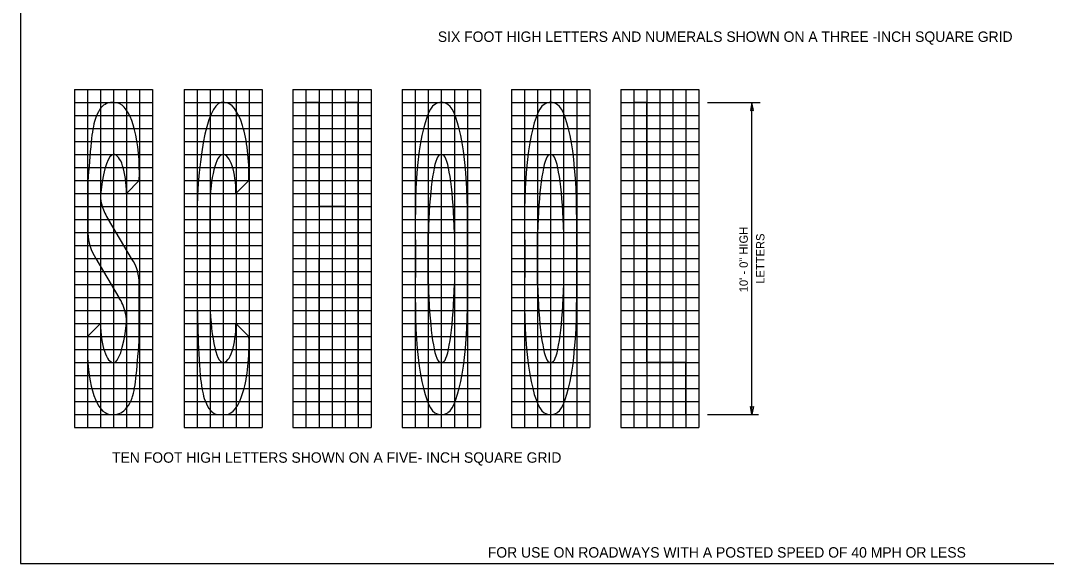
# Model space of a CAD drawing. Extents: x 99862 to 103151, y 100000 to 102076.
# Drawn here: x 99862 to 101833, y 100000 to 101043 of the extents above; entities that cross this region are included whole.
import ezdxf

# ---------------------------------------------------------------- set-up
doc = ezdxf.new("R2010")
doc.units = 0
for name, color, linetype in [('Level 1', 7, 'Continuous'), ('Level 15', 7, 'Continuous'), ('Level 20', 7, 'Continuous'), ('Level 4', 7, 'Continuous'), ('Level 60', 7, 'Continuous')]:
    doc.layers.add(name, color=color, linetype=linetype)

msp = doc.modelspace()

# ---------------------------------------------------------------- linework, layer by layer
at = {"layer": 'Level 1'}
msp.add_lwpolyline([(99862, 99999.5), (103151, 99999.5), (103151, 102075.5), (99862, 102075.5)], close=True, dxfattribs=at)
at = {"layer": 'Level 15'}
for p, q in [((101181.5, 100885.5), (101283.1, 100885.5)), ((101267.1, 100285.5), (101267.1, 100885.5)), ((101181.5, 100285.5), (101279.8, 100285.5))]:
    msp.add_line(p, q, dxfattribs=at)
for points in [[(101267.1, 100885.5), (101264.1, 100869.8), (101267.1, 100870.5), (101270.2, 100869.8)], [(101267.1, 100285.5), (101264.1, 100301.2), (101267.1, 100300.5), (101270.2, 100301.2)]]:
    msp.add_lwpolyline(points, close=True, dxfattribs=at)
at = {"layer": 'Level 20'}
for p, q in [((100254.1, 100885.5), (100247.5, 100885.5)), ((100065.6, 100710.5), (100090.2, 100735.5)), ((100275.9, 100710.5), (100300.8, 100735.5)), ((100226.1, 100510.5), (100226.1, 100685.5)), ((100075.5, 100585.5), (100031.3, 100660.2)), ((100620.4, 100658.9), (100620.5, 100585.5)), ((100720.4, 100585.5), (100720.4, 100658.9)), ((100830.4, 100658.9), (100830.5, 100585.5)), ((100830.4, 100658.9), (100830.5, 100585.5)), ((100930.4, 100585.5), (100930.4, 100658.9)), ((100930.4, 100585.5), (100930.4, 100658.9)), ((100201.2, 100635.5), (100201.2, 100535.5)), ((100645.4, 100585.5), (100645.4, 100633.9)), ((100695.4, 100633.9), (100695.4, 100585.5)), ((100855.4, 100585.5), (100855.4, 100633.9)), ((100855.4, 100585.5), (100855.4, 100633.9)), ((100905.4, 100633.9), (100905.4, 100585.5)), ((100905.4, 100633.9), (100905.4, 100585.5)), ((100006.9, 100585.5), (100050.9, 100510.9)), ((100620.5, 100585.5), (100620.4, 100512.1)), ((100645.4, 100537.1), (100645.4, 100585.5)), ((100695.4, 100585.5), (100695.4, 100537.1)), ((100720.4, 100512.1), (100720.4, 100585.5)), ((100830.5, 100585.5), (100830.4, 100512.1)), ((100830.5, 100585.5), (100830.4, 100512.1)), ((100855.4, 100537.1), (100855.4, 100585.5)), ((100855.4, 100537.1), (100855.4, 100585.5)), ((100905.4, 100585.5), (100905.4, 100537.1)), ((100905.4, 100585.5), (100905.4, 100537.1)), ((100930.4, 100512.1), (100930.4, 100585.5)), ((100930.4, 100512.1), (100930.4, 100585.5)), ((100015.8, 100460.5), (99990.9, 100435.5)), ((100300.8, 100435.5), (100275.9, 100460.5)), ((100244.3, 100285.5), (100256.6, 100285.5))]:
    msp.add_line(p, q, dxfattribs=at)
for points in [[(100485.4, 100685.5), (100435.4, 100685.5), (100435.4, 100885.5), (100410.4, 100885.5), (100410.4, 100285.5), (100435.4, 100285.5), (100435.4, 100585.5), (100485.4, 100585.5), (100485.4, 100285.5), (100510.4, 100285.5), (100510.4, 100885.5), (100485.4, 100885.5)], [(101065.4, 100385.5), (101065.4, 100885.5), (101040.4, 100885.5), (101040.4, 100285.5), (101062.3, 100285.5), (101065.4, 100285.5), (101140.4, 100285.5), (101140.4, 100385.5)]]:
    msp.add_lwpolyline(points, close=True, dxfattribs=at)
for centre, major_axis, ratio, start_param, end_param in [((100092.4, 100581.3), (63, -302.3), 0.242157, 3.211303, 3.548693), ((100039.2, 100873.6), (20.3, 0), 0.586221, 0.838796, 2.384773), ((100041.9, 100736.8), (-4.7, -147.1), 0.328163, 1.572424, 3.011418), ((100251.9, 100645.6), (2.3, -240.1), 0.211336, 3.181491, 4.752287), ((100250.9, 100736.3), (-3.3, -149.2), 0.334281, 1.57277, 3.143567), ((100670.4, 100635), (6.3, -249), 0.19927, 3.270148, 4.611013), ((100657.9, 100359.5), (-13.1, -526), 0.19927, 3.02647, 3.266464), ((100670.5, 100635.1), (-6.2, -248.8), 0.19927, 1.671693, 3.012646), ((100880.4, 100635), (6.3, -249), 0.19927, 3.270148, 4.611013), ((100880.4, 100635), (6.3, -249), 0.19927, 3.270148, 4.611013), ((100867.9, 100359.5), (-13.1, -526), 0.19927, 3.02647, 3.266464), ((100867.9, 100359.5), (-13.1, -526), 0.19927, 3.02647, 3.266464), ((100880.5, 100635.1), (-6.2, -248.8), 0.19927, 1.671693, 3.012646), ((100880.5, 100635.1), (-6.2, -248.8), 0.19927, 1.671693, 3.012646), ((100026.9, 100734.6), (9.3, -133.7), 0.214782, 3.612749, 4.104614), ((100081.3, 100593.6), (5, -434), 0.21476, 4.189874, 4.38199), ((100038.1, 100656.7), (-2.5, -128.8), 0.197234, 3.13878, 4.217516), ((100040.8, 100710.3), (0.1, -75.2), 0.328816, 1.572371, 3.143168), ((100251, 100685.5), (0, -100), 0.248912, 3.141593, 4.712389), ((100251, 100710.5), (0, -75), 0.331883, 1.570796, 3.141593), ((100663.8, 100633.5), (-3.5, -150.4), 0.122012, 3.268533, 4.71248), ((100660.5, 100351.2), (-10.2, -433.9), 0.122012, 3.042541, 3.248082), ((100677.1, 100633.5), (3.5, -150.4), 0.122012, 1.570705, 3.018849), ((100873.8, 100633.5), (-3.5, -150.4), 0.122012, 3.268533, 4.71248), ((100873.8, 100633.5), (-3.5, -150.4), 0.122012, 3.268533, 4.71248), ((100870.5, 100351.2), (-10.2, -433.9), 0.122012, 3.042541, 3.248082), ((100870.5, 100351.2), (-10.2, -433.9), 0.122012, 3.042541, 3.248082), ((100887.1, 100633.5), (3.5, -150.4), 0.122012, 1.570705, 3.018849), ((100887.1, 100633.5), (3.5, -150.4), 0.122012, 1.570705, 3.018849), ((100038.1, 100656.7), (-2.5, -128.8), 0.197234, 4.217516, 4.296738), ((100027.2, 100705.8), (0, -28.6), 0.398069, 4.656791, 5.485831), ((100038.1, 100656.7), (-2.5, -128.8), 0.197234, 4.296738, 4.302967), ((100258, 100763.3), (-237.7, -81.7), 0.573901, 6.095726, 6.102518), ((100258, 100763.3), (-237.7, -81.7), 0.573901, 6.252411, 6.448452), ((100235.7, 100684.6), (-240.1, -75.8), 0.590702, 6.109362, 6.45629), ((99846.3, 100488.7), (-240, -74), 0.588453, 2.958424, 3.311229), ((100332.5, 100654.3), (-29.1, -590.5), 0.216739, 4.925571, 5.243712), ((100663.8, 100537.5), (3.5, -150.4), 0.122012, 4.712298, 6.156245), ((100677.1, 100537.5), (-3.5, -150.4), 0.122012, 0.122744, 1.570888), ((100873.8, 100537.5), (3.5, -150.4), 0.122012, 4.712298, 6.156245), ((100873.8, 100537.5), (3.5, -150.4), 0.122012, 4.712298, 6.156245), ((100887.1, 100537.5), (-3.5, -150.4), 0.122012, 0.122744, 1.570888), ((100887.1, 100537.5), (-3.5, -150.4), 0.122012, 0.122744, 1.570888), ((99812.7, 100409.9), (-248.8, -79.1), 0.572533, 3.093706, 3.30331), ((100251, 100510.5), (0, -125), 0.19913, 4.712389, 6.283185), ((100670.4, 100536), (-6.3, -249), 0.19927, 4.813765, 6.15463), ((100670.5, 100535.9), (6.2, -248.8), 0.19927, 0.128946, 1.4699), ((100880.4, 100536), (-6.3, -249), 0.19927, 4.813765, 6.15463), ((100880.4, 100536), (-6.3, -249), 0.19927, 4.813765, 6.15463), ((100880.5, 100535.9), (6.2, -248.8), 0.19927, 0.128946, 1.4699), ((100880.5, 100535.9), (6.2, -248.8), 0.19927, 0.128946, 1.4699), ((100054.1, 100465.2), (0, -28.6), 0.398069, 1.570796, 2.201234), ((100040.6, 100461.1), (-0.1, -75.6), 0.328439, 4.720548, 6.291345), ((100054.1, 100465.2), (0, -28.6), 0.398069, 1.272104, 1.406781), ((100054.1, 100465.2), (0, -28.6), 0.398069, 1.406781, 1.536547), ((100054.1, 100465.2), (0, -28.6), 0.398069, 1.536547, 1.570796), ((100251, 100460.5), (0, -75), 0.331883, 6.283185, 7.853982), ((100044.4, 100509.4), (-3.7, -123.9), 0.197285, 6.281921, 7.420926), ((100039.1, 100433.9), (-7.1, -146.7), 0.327941, 4.716992, 6.122079), ((100002, 100571.1), (7.5, -422), 0.214743, 1.047686, 1.241737), ((100251.6, 100434.2), (5.1, -148.6), 0.331181, 6.280966, 7.851763), ((100660.5, 100819.8), (10.2, -433.9), 0.122012, 6.176696, 6.382237), ((100870.5, 100819.8), (10.2, -433.9), 0.122012, 6.176696, 6.382237), ((100870.5, 100819.8), (10.2, -433.9), 0.122012, 6.176696, 6.382237), ((100055.4, 100436.4), (9.3, -133.7), 0.214782, 0.471156, 0.963021), ((100236.7, 100435.7), (-9.4, -134.4), 0.216756, 5.320454, 5.812319), ((100009.1, 100606.7), (39.3, -319.7), 0.244883, 0.082568, 0.415625), ((100303.1, 100589.7), (-63.9, -303.8), 0.244216, 5.877043, 6.350091), ((100039.9, 100297.4), (21, 0), 0.567157, 3.879554, 5.494464), ((100657.9, 100811.5), (13.1, -526), 0.19927, 6.158314, 6.398307), ((100867.9, 100811.5), (13.1, -526), 0.19927, 6.158314, 6.398307), ((100867.9, 100811.5), (13.1, -526), 0.19927, 6.158314, 6.398307)]:
    msp.add_ellipse(centre, major_axis=major_axis, ratio=ratio, start_param=start_param, end_param=end_param, dxfattribs=at)
for points in [[(99991.5, 100733.4), (99990.9, 100641.8), (99991.5, 100634.5)], [(100090.2, 100436.3), (100090.2, 100534.2), (100090.2, 100535.8)]]:
    msp.add_open_spline(points, degree=2, dxfattribs=at)
at = {"layer": 'Level 4'}
for p, q in [((99965.4, 100910.5), (99965.4, 100260.5)), ((99965.4, 100910.5), (100115.4, 100910.5)), ((99990.4, 100910.5), (99990.4, 100260.5)), ((100015.4, 100910.5), (100015.4, 100260.5)), ((100040.4, 100910.5), (100040.4, 100260.5)), ((100065.4, 100910.5), (100065.4, 100260.5)), ((100090.4, 100910.5), (100090.4, 100260.5)), ((100115.4, 100910.5), (100115.4, 100260.5)), ((100176.1, 100910.5), (100176.1, 100260.5)), ((100176.1, 100910.5), (100326.1, 100910.5)), ((100201.1, 100910.5), (100201.1, 100260.5)), ((100226.1, 100910.5), (100226.1, 100260.5)), ((100251.1, 100910.5), (100251.1, 100260.5)), ((100276.1, 100910.5), (100276.1, 100260.5)), ((100301.1, 100910.5), (100301.1, 100260.5)), ((100326.1, 100910.5), (100326.1, 100260.5)), ((100385.4, 100910.5), (100385.4, 100260.5)), ((100385.4, 100910.5), (100535.4, 100910.5)), ((100410.4, 100910.5), (100410.4, 100260.5)), ((100435.4, 100910.5), (100435.4, 100260.5)), ((100460.4, 100910.5), (100460.4, 100260.5)), ((100485.4, 100910.5), (100485.4, 100260.5)), ((100510.4, 100910.5), (100510.4, 100260.5)), ((100535.4, 100910.5), (100535.4, 100260.5)), ((100595.4, 100910.5), (100595.4, 100260.5)), ((100595.4, 100910.5), (100745.4, 100910.5)), ((100620.4, 100910.5), (100620.4, 100260.5)), ((100645.4, 100910.5), (100645.4, 100260.5)), ((100670.4, 100910.5), (100670.4, 100260.5)), ((100695.4, 100910.5), (100695.4, 100260.5)), ((100720.4, 100910.5), (100720.4, 100260.5)), ((100745.4, 100910.5), (100745.4, 100260.5)), ((100805.4, 100910.5), (100805.4, 100260.5)), ((100805.4, 100910.5), (100955.4, 100910.5)), ((100805.4, 100910.5), (100805.4, 100260.5)), ((100805.4, 100910.5), (100955.4, 100910.5)), ((100830.4, 100910.5), (100830.4, 100260.5)), ((100830.4, 100910.5), (100830.4, 100260.5)), ((100855.4, 100910.5), (100855.4, 100260.5)), ((100855.4, 100910.5), (100855.4, 100260.5)), ((100880.4, 100910.5), (100880.4, 100260.5)), ((100880.4, 100910.5), (100880.4, 100260.5)), ((100905.4, 100910.5), (100905.4, 100260.5)), ((100905.4, 100910.5), (100905.4, 100260.5)), ((100930.4, 100910.5), (100930.4, 100260.5)), ((100930.4, 100910.5), (100930.4, 100260.5)), ((100955.4, 100910.5), (100955.4, 100260.5)), ((100955.4, 100910.5), (100955.4, 100260.5)), ((101015.4, 100910.5), (101015.4, 100260.5)), ((101015.4, 100910.5), (101165.4, 100910.5)), ((101040.4, 100910.5), (101040.4, 100260.5)), ((101065.4, 100910.5), (101065.4, 100260.5)), ((101090.4, 100910.5), (101090.4, 100260.5)), ((101115.4, 100910.5), (101115.4, 100260.5)), ((101140.4, 100910.5), (101140.4, 100260.5)), ((101165.4, 100910.5), (101165.4, 100260.5)), ((99965.4, 100885.5), (100115.4, 100885.5)), ((100176.1, 100885.5), (100326.1, 100885.5)), ((100385.4, 100885.5), (100535.4, 100885.5)), ((100595.4, 100885.5), (100745.4, 100885.5)), ((100805.4, 100885.5), (100955.4, 100885.5)), ((100805.4, 100885.5), (100955.4, 100885.5)), ((101015.4, 100885.5), (101165.4, 100885.5)), ((99965.4, 100860.5), (100115.4, 100860.5)), ((100176.1, 100860.5), (100326.1, 100860.5)), ((100385.4, 100860.5), (100535.4, 100860.5)), ((100595.4, 100860.5), (100745.4, 100860.5)), ((100805.4, 100860.5), (100955.4, 100860.5)), ((100805.4, 100860.5), (100955.4, 100860.5)), ((101015.4, 100860.5), (101165.4, 100860.5)), ((99965.4, 100835.5), (100115.4, 100835.5)), ((100176.1, 100835.5), (100326.1, 100835.5)), ((100385.4, 100835.5), (100535.4, 100835.5)), ((100595.4, 100835.5), (100745.4, 100835.5)), ((100805.4, 100835.5), (100955.4, 100835.5)), ((100805.4, 100835.5), (100955.4, 100835.5)), ((101015.4, 100835.5), (101165.4, 100835.5)), ((99965.4, 100810.5), (100115.4, 100810.5)), ((100176.1, 100810.5), (100326.1, 100810.5)), ((100385.4, 100810.5), (100535.4, 100810.5)), ((100595.4, 100810.5), (100745.4, 100810.5)), ((100805.4, 100810.5), (100955.4, 100810.5)), ((100805.4, 100810.5), (100955.4, 100810.5)), ((101015.4, 100810.5), (101165.4, 100810.5)), ((99965.4, 100785.5), (100115.4, 100785.5)), ((100176.1, 100785.5), (100326.1, 100785.5)), ((100385.4, 100785.5), (100535.4, 100785.5)), ((100595.4, 100785.5), (100745.4, 100785.5)), ((100805.4, 100785.5), (100955.4, 100785.5)), ((100805.4, 100785.5), (100955.4, 100785.5)), ((101015.4, 100785.5), (101165.4, 100785.5)), ((99965.4, 100760.5), (100115.4, 100760.5)), ((100176.1, 100760.5), (100326.1, 100760.5)), ((100385.4, 100760.5), (100535.4, 100760.5)), ((100595.4, 100760.5), (100745.4, 100760.5)), ((100805.4, 100760.5), (100955.4, 100760.5)), ((100805.4, 100760.5), (100955.4, 100760.5)), ((101015.4, 100760.5), (101165.4, 100760.5)), ((99965.4, 100735.5), (100115.4, 100735.5)), ((100176.1, 100735.5), (100326.1, 100735.5)), ((100385.4, 100735.5), (100535.4, 100735.5)), ((100595.4, 100735.5), (100745.4, 100735.5)), ((100805.4, 100735.5), (100955.4, 100735.5)), ((100805.4, 100735.5), (100955.4, 100735.5)), ((101015.4, 100735.5), (101165.4, 100735.5)), ((99965.4, 100710.5), (100115.4, 100710.5)), ((100176.1, 100710.5), (100326.1, 100710.5)), ((100385.4, 100710.5), (100535.4, 100710.5)), ((100595.4, 100710.5), (100745.4, 100710.5)), ((100805.4, 100710.5), (100955.4, 100710.5)), ((100805.4, 100710.5), (100955.4, 100710.5)), ((101015.4, 100710.5), (101165.4, 100710.5)), ((99965.4, 100685.5), (100115.4, 100685.5)), ((100176.1, 100685.5), (100326.1, 100685.5)), ((100385.4, 100685.5), (100535.4, 100685.5)), ((100595.4, 100685.5), (100745.4, 100685.5)), ((100805.4, 100685.5), (100955.4, 100685.5)), ((100805.4, 100685.5), (100955.4, 100685.5)), ((101015.4, 100685.5), (101165.4, 100685.5)), ((99965.4, 100660.5), (100115.4, 100660.5)), ((100176.1, 100660.5), (100326.1, 100660.5)), ((100385.4, 100660.5), (100535.4, 100660.5)), ((100595.4, 100660.5), (100745.4, 100660.5)), ((100805.4, 100660.5), (100955.4, 100660.5)), ((100805.4, 100660.5), (100955.4, 100660.5)), ((101015.4, 100660.5), (101165.4, 100660.5)), ((99965.4, 100635.5), (100115.4, 100635.5)), ((100176.1, 100635.5), (100326.1, 100635.5)), ((100385.4, 100635.5), (100535.4, 100635.5)), ((100595.4, 100635.5), (100745.4, 100635.5)), ((100805.4, 100635.5), (100955.4, 100635.5)), ((100805.4, 100635.5), (100955.4, 100635.5)), ((101015.4, 100635.5), (101165.4, 100635.5)), ((99965.4, 100610.5), (100115.4, 100610.5)), ((100176.1, 100610.5), (100326.1, 100610.5)), ((100385.4, 100610.5), (100535.4, 100610.5)), ((100595.4, 100610.5), (100745.4, 100610.5)), ((100805.4, 100610.5), (100955.4, 100610.5)), ((100805.4, 100610.5), (100955.4, 100610.5)), ((101015.4, 100610.5), (101165.4, 100610.5)), ((99965.4, 100585.5), (100115.4, 100585.5)), ((100176.1, 100585.5), (100326.1, 100585.5)), ((100385.4, 100585.5), (100535.4, 100585.5)), ((100595.4, 100585.5), (100745.4, 100585.5)), ((100805.4, 100585.5), (100955.4, 100585.5)), ((100805.4, 100585.5), (100955.4, 100585.5)), ((101015.4, 100585.5), (101165.4, 100585.5)), ((99965.4, 100560.5), (100115.4, 100560.5)), ((100176.1, 100560.5), (100326.1, 100560.5)), ((100385.4, 100560.5), (100535.4, 100560.5)), ((100595.4, 100560.5), (100745.4, 100560.5)), ((100805.4, 100560.5), (100955.4, 100560.5)), ((100805.4, 100560.5), (100955.4, 100560.5)), ((101015.4, 100560.5), (101165.4, 100560.5)), ((99965.4, 100535.5), (100115.4, 100535.5)), ((100176.1, 100535.5), (100326.1, 100535.5)), ((100385.4, 100535.5), (100535.4, 100535.5)), ((100595.4, 100535.5), (100745.4, 100535.5)), ((100805.4, 100535.5), (100955.4, 100535.5)), ((100805.4, 100535.5), (100955.4, 100535.5)), ((101015.4, 100535.5), (101165.4, 100535.5)), ((99965.4, 100510.5), (100115.4, 100510.5)), ((100176.1, 100510.5), (100326.1, 100510.5)), ((100385.4, 100510.5), (100535.4, 100510.5)), ((100595.4, 100510.5), (100745.4, 100510.5)), ((100805.4, 100510.5), (100955.4, 100510.5)), ((100805.4, 100510.5), (100955.4, 100510.5)), ((101015.4, 100510.5), (101165.4, 100510.5)), ((99965.4, 100485.5), (100115.4, 100485.5)), ((100176.1, 100485.5), (100326.1, 100485.5)), ((100385.4, 100485.5), (100535.4, 100485.5)), ((100595.4, 100485.5), (100745.4, 100485.5)), ((100805.4, 100485.5), (100955.4, 100485.5)), ((100805.4, 100485.5), (100955.4, 100485.5)), ((101015.4, 100485.5), (101165.4, 100485.5)), ((99965.4, 100460.5), (100115.4, 100460.5)), ((100176.1, 100460.5), (100326.1, 100460.5)), ((100385.4, 100460.5), (100535.4, 100460.5)), ((100595.4, 100460.5), (100745.4, 100460.5)), ((100805.4, 100460.5), (100955.4, 100460.5)), ((100805.4, 100460.5), (100955.4, 100460.5)), ((101015.4, 100460.5), (101165.4, 100460.5)), ((99965.4, 100435.5), (100115.4, 100435.5)), ((100176.1, 100435.5), (100326.1, 100435.5)), ((100385.4, 100435.5), (100535.4, 100435.5)), ((100595.4, 100435.5), (100745.4, 100435.5)), ((100805.4, 100435.5), (100955.4, 100435.5)), ((100805.4, 100435.5), (100955.4, 100435.5)), ((101015.4, 100435.5), (101165.4, 100435.5)), ((99965.4, 100410.5), (100115.4, 100410.5)), ((100176.1, 100410.5), (100326.1, 100410.5)), ((100385.4, 100410.5), (100535.4, 100410.5)), ((100595.4, 100410.5), (100745.4, 100410.5)), ((100805.4, 100410.5), (100955.4, 100410.5)), ((100805.4, 100410.5), (100955.4, 100410.5)), ((101015.4, 100410.5), (101165.4, 100410.5)), ((99965.4, 100385.5), (100115.4, 100385.5)), ((100176.1, 100385.5), (100326.1, 100385.5)), ((100385.4, 100385.5), (100535.4, 100385.5)), ((100595.4, 100385.5), (100745.4, 100385.5)), ((100805.4, 100385.5), (100955.4, 100385.5)), ((100805.4, 100385.5), (100955.4, 100385.5)), ((101015.4, 100385.5), (101165.4, 100385.5)), ((99965.4, 100360.5), (100115.4, 100360.5)), ((100176.1, 100360.5), (100326.1, 100360.5)), ((100385.4, 100360.5), (100535.4, 100360.5)), ((100595.4, 100360.5), (100745.4, 100360.5)), ((100805.4, 100360.5), (100955.4, 100360.5)), ((100805.4, 100360.5), (100955.4, 100360.5)), ((101015.4, 100360.5), (101165.4, 100360.5)), ((99965.4, 100335.5), (100115.4, 100335.5)), ((100176.1, 100335.5), (100326.1, 100335.5)), ((100385.4, 100335.5), (100535.4, 100335.5)), ((100595.4, 100335.5), (100745.4, 100335.5)), ((100805.4, 100335.5), (100955.4, 100335.5)), ((100805.4, 100335.5), (100955.4, 100335.5)), ((101015.4, 100335.5), (101165.4, 100335.5)), ((99965.4, 100310.5), (100115.4, 100310.5)), ((100176.1, 100310.5), (100326.1, 100310.5)), ((100385.4, 100310.5), (100535.4, 100310.5)), ((100595.4, 100310.5), (100745.4, 100310.5)), ((100805.4, 100310.5), (100955.4, 100310.5)), ((100805.4, 100310.5), (100955.4, 100310.5)), ((101015.4, 100310.5), (101165.4, 100310.5)), ((99965.4, 100285.5), (100115.4, 100285.5)), ((100176.1, 100285.5), (100326.1, 100285.5)), ((100385.4, 100285.5), (100535.4, 100285.5)), ((100595.4, 100285.5), (100745.4, 100285.5)), ((100805.4, 100285.5), (100955.4, 100285.5)), ((100805.4, 100285.5), (100955.4, 100285.5)), ((101015.4, 100285.5), (101165.4, 100285.5)), ((99965.4, 100260.5), (100115.4, 100260.5)), ((100176.1, 100260.5), (100326.1, 100260.5)), ((100385.4, 100260.5), (100535.4, 100260.5)), ((100595.4, 100260.5), (100745.4, 100260.5)), ((100805.4, 100260.5), (100955.4, 100260.5)), ((100805.4, 100260.5), (100955.4, 100260.5)), ((101015.4, 100260.5), (101165.4, 100260.5))]:
    msp.add_line(p, q, dxfattribs=at)
at = {"layer": 'Level 60'}
msp.add_line((99862, 99999.5), (99862, 99999.5), dxfattribs=at)

# ---------------------------------------------------------------- texts
at = {"layer": 'Level 20'}
for s, p in [('SIX FOOT HIGH LETTERS AND NUMERALS SHOWN ON A THREE -INCH SQUARE GRID', (100663.7, 101001.8)), ('TEN FOOT HIGH LETTERS SHOWN ON A FIVE- INCH SQUARE GRID', (100037.8, 100193.1)), ('FOR USE ON ROADWAYS WITH A POSTED SPEED OF 40 MPH OR LESS', (100759.7, 100010.8))]:
    msp.add_text(s, height=20, dxfattribs=at).set_placement(p)
for s, p in [('10\' - 0" HIGH', (101259.1, 100520.7)), ('LETTERS', (101291.1, 100537.2))]:
    msp.add_text(s, height=16, rotation=90, dxfattribs=at).set_placement(p)

doc.saveas('drawing.dxf')
